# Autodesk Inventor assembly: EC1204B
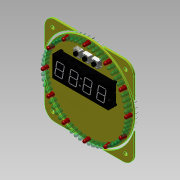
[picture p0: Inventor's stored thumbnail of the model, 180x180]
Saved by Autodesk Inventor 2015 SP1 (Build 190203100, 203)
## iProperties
Created: 2015-05
Part Number: EC1204B
Document SubType Name: Assembly
Designer: kazys
Author: kazys
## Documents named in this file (7)
- C:\Users\kazys\Documents\Inventor\Clock\Clock Board Assy.iam
- C:\Users\kazys\Documents\Inventor\Clock\Clock board.ipt
- C:\Users\kazys\Documents\Inventor\Clock\MOLEX_0678038020.ipt
- C:\Users\kazys\Documents\Inventor\Clock\HDSP-B0xE Avago Tech LED clock disp.ipt
- C:\Users\kazys\Documents\Inventor\Clock\LED red 3mm.ipt
- C:\Users\kazys\Documents\Inventor\Clock\LED grn 3mm.ipt
- C:\Users\kazys\Documents\Inventor\Clock\B3F_1020.iam
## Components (66 placed, 6 different names)
1. Clock board:1 — Mate:3, Mate:5, Flush:2, Mate:6, Flush:3, Flush:4, Mate:7, Flush:6, Flush:7, Mate:8, Flush:8
2. MOLEX_0678038020:1
3. HDSP-B0xE Avago Tech LED clock disp:1
4. B3F_1020:1 [sub-assembly] — Flush:2, Mate:6, Flush:3
5. B3F_1020:2 [sub-assembly] — Flush:4, Mate:7, Flush:6
6. B3F_1020:3 [sub-assembly] — Flush:7, Mate:8, Flush:8
7. LED red 3mm:1 — Mate:3
8. LED red 3mm:2
9. LED red 3mm:3
10. LED red 3mm:4
11. LED red 3mm:5
12. LED red 3mm:6
13. LED red 3mm:7
14. LED red 3mm:8
15. LED red 3mm:9
16. LED red 3mm:10
17. LED red 3mm:11
18. LED red 3mm:12
19. LED grn 3mm:1 — Mate:5
20. LED grn 3mm:2
21. LED grn 3mm:3
22. LED grn 3mm:4
23. LED grn 3mm:5
24. LED grn 3mm:6
25. LED grn 3mm:7
26. LED grn 3mm:8
27. LED grn 3mm:9
28. LED grn 3mm:10
29. LED grn 3mm:11
30. LED grn 3mm:12
31. LED grn 3mm:13
32. LED grn 3mm:14
33. LED grn 3mm:15
34. LED grn 3mm:16
35. LED grn 3mm:17
36. LED grn 3mm:18
37. LED grn 3mm:19
38. LED grn 3mm:20
39. LED grn 3mm:21
40. LED grn 3mm:22
41. LED grn 3mm:23
42. LED grn 3mm:24
43. LED grn 3mm:25
44. LED grn 3mm:26
45. LED grn 3mm:27
46. LED grn 3mm:28
47. LED grn 3mm:29
48. LED grn 3mm:30
49. LED grn 3mm:31
50. LED grn 3mm:32
51. LED grn 3mm:33
52. LED grn 3mm:34
53. LED grn 3mm:35
54. LED grn 3mm:36
55. LED grn 3mm:37
56. LED grn 3mm:38
57. LED grn 3mm:39
58. LED grn 3mm:40
59. LED grn 3mm:41
60. LED grn 3mm:42
61. LED grn 3mm:43
62. LED grn 3mm:44
63. LED grn 3mm:45
64. LED grn 3mm:46
65. LED grn 3mm:47
66. LED grn 3mm:48
## Component patterns: Component Pattern 2:2 (4 elements), Component Pattern 2:3 (4 elements), Component Pattern 2:4 (4 elements), Component Pattern 2:5 (4 elements), Component Pattern 2:6 (4 elements), Component Pattern 2:7 (4 elements), Component Pattern 2:8 (4 elements), Component Pattern 2:9 (4 elements), Component Pattern 2:10 (4 elements), Component Pattern 2:11 (4 elements), Component Pattern 2:12 (4 elements)
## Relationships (11: Flush 6, Mate 5)
- Mate:3: Clock board:1 ↔ LED red 3mm:1
- Mate:5: Clock board:1 ↔ LED grn 3mm:1
- Flush:2: Clock board:1 ↔ B3F_1020:1
- Mate:6: Clock board:1 ↔ B3F_1020:1
- Flush:3: Clock board:1 ↔ B3F_1020:1
- Flush:4: Clock board:1 ↔ B3F_1020:2
- Mate:7: Clock board:1 ↔ B3F_1020:2
- Flush:6: Clock board:1 ↔ B3F_1020:2
- Flush:7: Clock board:1 ↔ B3F_1020:3
- Mate:8: Clock board:1 ↔ B3F_1020:3
- Flush:8: Clock board:1 ↔ B3F_1020:3
